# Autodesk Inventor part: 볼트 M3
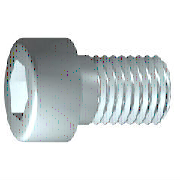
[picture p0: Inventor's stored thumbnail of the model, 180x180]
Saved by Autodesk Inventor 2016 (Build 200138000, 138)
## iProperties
IsCustomPart: 0
Created: 2012-02
Part Number: 볼트 M3
Material: 스테인리스강
Description: 6각 소켓 머리 캡 나사
Document SubType Name: Modeling
Standard: ISO 4762
Designer: mduedu
Standard Revision: Fourth edition 2004-03-01
Standards Organization: ISO
Language: ko-KR
Size Designation: M3 x 8
Categories: <MemberInstance><Categories><Category DisplayName="조임쇠" InternalName="e4da775c-781d-43d5-af7c-5136215cf5a6" Mnemonic="FSTN"><Category DisplayName="볼트" InternalN
Density: 7.75 g/cm^3
Appearance: 반광택
Author: mduedu
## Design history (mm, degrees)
sketch "스케치1"
  geometry: L1 (-0.867, 0)-(8, 0); L2 (8, 0)-(8, 1.5); L3 (8, 1.5)-(1.25, 1.5); L4 (1.25, 1.5)-(0.943, 1.5); L5 (0.943, 1.5)-(0, 1.5); L6 (0, 1.5)-(0, 2.75); L7 (0, 2.75)-(-3, 2.75); L8 (-3, 2.75)-(-3, 1.443); L9 (-3, 1.443)-(-1.7, 1.443); L10 (-1.7, 1.443)-(-0.867, 0); L11 (-5.2, 0)-(10.2, 0) reference; L12 (0, -0.55)-(0, 3.3) reference; L13 (1.25, 1.5)-(0, 1.5)
  constraints: 22 end point, 6 parallel, 2 collinear, 2 perpendicular, 1 horizontal, 1 point on line
  dimensions: "d1" = 6.75 distance from line of L3.end L2 (= GEL); "d2" = 0.30683 distance of L4.end L3.end (computed from GAL); "d3" = 3 distance between parallel lines of L8 L6 (= KOH); "d4" = 1.3 distance of L8.end L9.end (= INTI); "d5" = 60 deg angle of L10 L1; "d6" = 3 diameter of L3 L1 (= GD); "d7" = 3 diameter of L5 L1 (= BDM); "d8" = 2.88675 diameter of L9 L1 (= 1.1547 x SW); "d9" = 5.5 diameter of L7 L1 (= KOD); "d26" = 8 distance between parallel lines of L12 L2 (= NLG)
revolve "본체" sketch "스케치1" stored, may be unused: angle "d10" = 90 deg
sketch "스케치2"
  geometry: L1 (0, -3.85)-(0, 3.85) reference; L2 (-3.85, 0)-(3.85, 0) reference; L3 (1.443, 0)-(0.722, -1.25); L4 (0.722, -1.25)-(-0.722, -1.25); L5 (-0.722, -1.25)-(-1.443, 0); L6 (-1.443, 0)-(-0.722, 1.25); L7 (-0.722, 1.25)-(0.722, 1.25); L8 (0.722, 1.25)-(1.443, 0); 2 further points
  constraints: 12 end point, 1 coincident, 1 horizontal alignment, 1 point on line, 12 other
extrude "슬롯" join sketch "스케치2" stored distance "d11" = 10; taper "d12" = 0 deg
workplane "Work Plane1"
fillet "Fillet2" dims "d30" = 0.1 (= R)
body "Solid1"
fillet "모깎기1" dims "d17" = 0.3 (= RR)
feature "스레드" dims "d13" = 6.75 (= GEL), "d14" = 0
chamfer "모따기1" distance "d15" = 0.30673 (= -0.5 x SPD + 0.5 x GD); stored, may be unused: second distance "d16" = 0.30673 (= GUL), angle "d27" = 45 deg
other parameters: "GD" = 3 [user parameter; used in 2 equation terms], "NLG" = 8 [user parameter; used in 1 equation term], "GEL" = 6.75 [user parameter; used in 2 equation terms], "KOD" = 5.5 [user parameter; used in 1 equation term], "KOH" = 3 [user parameter; used in 1 equation term], "INTI" = 1.3 [user parameter; used in 1 equation term], "GAL" = 0.30673 (= 0.61345 x PTC) [user parameter; used in 1 equation term], "GUL" = 0.30673 (= 0.61345 x PTC) [user parameter; used in 1 equation term], "BDM" = 3 (= NND) [user parameter; used in 1 equation term], "SW" = 2.5 [user parameter; used in 2 equation terms], "RR" = 0.3 [user parameter; used in 1 equation term], "SPD" = 2.38655 (= NND - 1.2269 x PTC) [user parameter; used in 1 equation term], "d19" = 0, "d28" = 0, "d29" = 0, "R" = 0.1 [user parameter; used in 1 equation term], "TOA" = 30 deg [user parameter], "GD1" = 2.38655 (= THREADDIA - 1.2269 x PTC) [user parameter], "THREADDIA" = 3 [user parameter; used in 1 equation term], "FAWI" = 45 deg [user parameter], "PTC" = 0.5 [user parameter; used in 5 equation terms], "NND" = 3 [user parameter; used in 2 equation terms], "E0" = 2.8875 (= 1.155 x SW) [user parameter]
